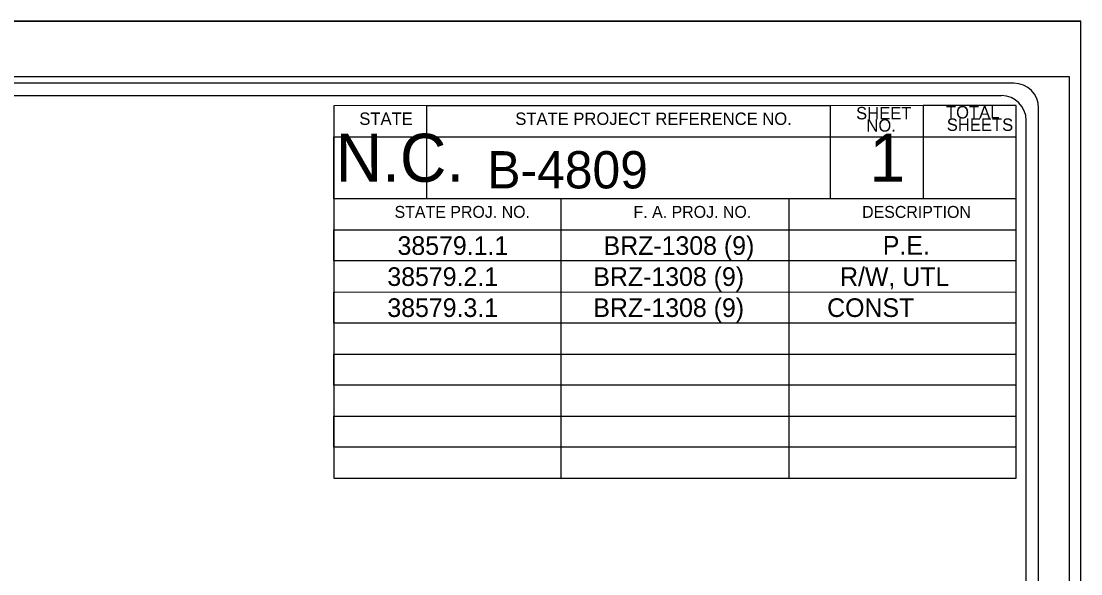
# Model space of a CAD drawing. Extents: x 1530800 to 1534168, y 642962 to 645162.
# Drawn here: x 1533314 to 1534168, y 644717 to 645162 of the extents above; entities that cross this region are included whole.
import ezdxf

# ---------------------------------------------------------------- set-up
doc = ezdxf.new("R2010")
doc.units = 0
for name, color, linetype in [('Sheet Cutting Line CELL', 7, 'Continuous'), ('Sheet Data Field CELL', 7, 'Continuous'), ('Sheet Plot Border Inside CELL', 7, 'Continuous'), ('Sheet Plot Border Outside CELL', 7, 'Continuous'), ('Sheet Title CELL', 7, 'Continuous')]:
    doc.layers.add(name, color=color, linetype=linetype)

msp = doc.modelspace()

# ---------------------------------------------------------------- linework, layer by layer
at = {"layer": 'Sheet Cutting Line CELL'}
msp.add_line((1530800.37, 645162.28), (1534168.37, 645162.28), dxfattribs=at)
at = {"layer": 'Sheet Plot Border Inside CELL'}
msp.add_lwpolyline([(1530826.37, 643007.18), (1534159.37, 643007.18), (1534159.37, 645117.38), (1530826.37, 645117.38)], close=True, dxfattribs=at)
at = {"layer": 'Sheet Plot Border Outside CELL'}
for p, q in [((1534168.37, 645162.28), (1530800.37, 645162.28)), ((1534168.37, 642962.3), (1534168.37, 645162.28))]:
    msp.add_line(p, q, dxfattribs=at)
at = {"layer": 'Sheet Title CELL'}
for points in [[(1534114.39, 645112.28), (1531154.34, 645112.3)], [(1534104.37, 645102.28), (1531264.39, 645102.28)], [(1533566.37, 644794.3), (1534116.37, 644794.3), (1534116.37, 644819.28), (1533566.37, 644819.3), (1533566.37, 644844.28), (1534116.37, 644844.28), (1534116.37, 644869.28), (1533566.39, 644869.28), (1533566.37, 644894.3), (1534116.37, 644894.3), (1534116.37, 644919.3), (1533566.37, 644919.3), (1533566.37, 644944.28), (1534116.37, 644944.3), (1534116.37, 644969.28), (1533566.37, 644969.28), (1533566.37, 644994.28), (1534116.37, 644994.28), (1534116.37, 645019.3), (1533566.37, 645019.3), (1533566.37, 645069.3), (1534116.37, 645069.3), (1534116.37, 645094.3), (1533566.37, 645094.28), (1533566.37, 644794.3), (1533749.67, 644794.28), (1533749.67, 645019.28), (1533641.37, 645019.28), (1533641.37, 645094.3), (1533966.39, 645094.28), (1533966.37, 645019.3), (1533932.97, 645019.3), (1533932.97, 644794.3), (1534116.37, 644794.3), (1534116.37, 645094.3), (1534041.37, 645094.3), (1534041.39, 645019.3)], [(1534134.37, 643032.3), (1534134.37, 645092.28)], [(1534124.37, 643412.28), (1534124.37, 645082.3)]]:
    msp.add_lwpolyline(points, dxfattribs=at)
for centre in [(1534114.37, 645092.39), (1534104.37, 645082.39)]:
    msp.add_arc(centre, 20, 0, 90, dxfattribs=at)

# ---------------------------------------------------------------- texts
at = {"layer": 'Sheet Data Field CELL'}
for s, height, p in [('B-4809    ', 30, (1533690.08, 645027.68)), ('38579.1.1', 15, (1533617.67, 644974.18)), ('BRZ-1308 (9)', 15, (1533783.73, 644974.18)), ('P.E.', 15, (1534008.78, 644974.38)), ('38579.2.1 ', 15, (1533609.48, 644949.18)), ('BRZ-1308 (9)  ', 15, (1533775.48, 644949.18)), ('R/W, UTL  ', 15, (1533974.35, 644949.2)), ('38579.3.1 ', 15, (1533609.48, 644924.2)), ('BRZ-1308 (9)  ', 15, (1533775.48, 644924.2)), ('CONST     ', 15, (1533963.92, 644924.2))]:
    msp.add_text(s, height=height, dxfattribs=at).set_placement(p)
at = {"layer": 'Sheet Title CELL'}
for s, height, p in [('SHEET', 10, (1533987.27, 645083.28)), ('TOTAL', 10, (1534059.67, 645084)), ('STATE', 10, (1533586.87, 645078.8)), ('STATE PROJECT REFERENCE NO.', 9.9996, (1533712.57, 645078.78)), ('NO.', 10, (1533995.57, 645073.4)), ('SHEETS', 10, (1534060.34, 645074)), ('N.C.', 38.7, (1533567.87, 645033)), ('1', 38.7, (1533998.07, 645033)), ('STATE PROJ. NO.', 9.6, (1533615.27, 645004)), ('F. A. PROJ. NO.', 9.6, (1533807.87, 645004)), ('DESCRIPTION', 9.6, (1533992.07, 645003.98))]:
    msp.add_text(s, height=height, dxfattribs=at).set_placement(p)

doc.saveas('drawing.dxf')
